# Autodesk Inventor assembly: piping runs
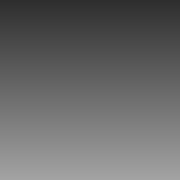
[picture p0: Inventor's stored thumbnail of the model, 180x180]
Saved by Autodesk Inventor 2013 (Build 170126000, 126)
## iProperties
ActiveState: False
BendRadius: UnInitValue
CouplingKey: v3#d2599e7a-1865-48da-a234-5418a1cd5dfe#3
DefaultBendRadius: UnInitValue
Diameter: 1/2
DiameterType: Nominal
Elbow45Key: v3#6ce5b1be-37aa-4928-b23a-0df64e6ddf38#2
Elbow90Key: v3#9fba244e-81ed-4fc6-a9ac-7eb372fa3ffe#3
ElbowCustomKey: UnInitValue
EndFittingKey: UnInitValue
Ending: UnInitValue
FittingMaterial: UnInitValue
FittingStandard: UnInitValue
FlangeKey: UnInitValue
Gap: UnInitValue
GasketKey: UnInitValue
ID: UnInitValue
IntermediateSegmentsInc: 2,540 mm
IntermediateSegmentsMax: 5080,000 mm
IntermediateSegmentsMin: 50,800 mm
IsButtWelded: False
IsFlanged: False
IsSelfDraining: False
Material: UnInitValue
MixedUnits: False
Name: DIN 2458/DIN EN 10242 - Stahlrohr mit Gewinde und Stahl-Fittings
OD: UnInitValue
PipeKey: v3#d689fd5f-ac5a-46d7-a883-3089b2f6e0a4#28
PipeType: Rigid Pipe
PipingComponentColor: As Material
RoundUpValue: UnInitValue
RouteDirection45: True
RouteDirection90: True
Schedule: ID=12.3
ShowGap: UnInitValue
Standard: UnInitValue
StartFittingKey: UnInitValue
SuppressEndFitting: UnInitValue
SuppressStartFitting: UnInitValue
TerminationSegmentsInc: 2,540 mm
TerminationSegmentsMax: 5080,000 mm
TerminationSegmentsMin: 50,800 mm
UseFlangsForCouplings: UnInitValue
UseSubASM: UnInitValue
_ComponentInfo: <CS><C N="Pipe" R="1.065000" IR="0.615000" PL="PL" PN="DIN 2458 Pipe with Threaded Ends 21.3 x 4.5"><CO N="1"><FE V="0"/><FD V="1"/><ET V="Threaded"/><NS V="1/2
CouplingKey: v3#eaa8de87-dc67-4eca-ba7e-4267a30f8f7f#2
Diameter: M40
Elbow45Key: v3#2769403e-a4fd-4a4c-8e4c-659ea845bd78#2
Elbow90Key: v3#c4513a61-3106-4a78-baf9-a1badd100245#2
IntermediateSegmentsInc: 1,000 mm
IntermediateSegmentsMax: 2500,000 mm
IntermediateSegmentsMin: 60,000 mm
Name: JIS K 6741/JIS K 6739 - Verbundenes PVC-U-Rohr und Fittings
PipeKey: v3#45338dd0-af69-48c0-a2ed-8ade33a08701#5
Schedule: VP
TerminationSegmentsInc: 1,000 mm
TerminationSegmentsMax: 2500,000 mm
TerminationSegmentsMin: 60,000 mm
_ComponentInfo: <CS><C N="Pipe" R="2.400000" IR="2.040000" PL="PL" PN="JIS K 6741 Pipe VP 40"><CO N="1"><FE V="0"/><FD V="1"/><ET V="Jointed"/><NS V="M40"/><MA V="4.000000"/><M
CouplingKey: v3#12b64993-10e6-4915-8315-0c0cce209ad0#8
Elbow45Key: v3#28e76e79-e22c-40ab-8be2-ff545b1407c5#8
Elbow90Key: v3#1f65ece3-c41a-48d4-8661-909ed34ade86#8
IntermediateSegmentsMax: 5000,000 mm
Name: JIS G 3458/JIS B 2316 -  Geschweißtes Stahlrohr und Fittings
PipeKey: v3#da14b0ab-0b36-4851-8d66-8c9cd0bcbe86#23
Schedule: 80
TerminationSegmentsMax: 5000,000 mm
_ComponentInfo: <CS><C N="Pipe" R="2.430000" IR="1.920000" PL="PL" PN="JIS G 3458 Pipe 40 A x Sch 80"><CO N="1"><FE V="0"/><FD V="1"/><ET V="Welded"/><NS V="M40"/><MA V="0.0000
Elbow45Key: v3#81684a3f-f2a4-4fe6-95b1-f067ddead22f#1
Elbow90Key: v3#451ae64e-c79d-4cba-b533-c09b8090ecb2#1
IntermediateSegmentsInc: 10,000 mm
IntermediateSegmentsMax: 9000,000 mm
IntermediateSegmentsMin: 1000,000 mm
Name: ISO 2531 - Geflanschtes, verformbares Stahlrohr und Fittings
PipeKey: v3#f52fbdcb-ece8-4303-8b76-5dbe8c7f2f9c#16
Schedule: PN10
TerminationSegmentsInc: 10,000 mm
TerminationSegmentsMax: 9000,000 mm
TerminationSegmentsMin: 1000,000 mm
_ComponentInfo: <CS><C N="Pipe" R="2.700000" IR="2.000000" PL="PL" PN="ISO 2531 Pipe with Integrally Cast Flanges DN40 PN 10"><CO N="1"><FE V="0"/><FD V="0"/><ET V="Flanged"/><
CouplingKey: v3#181262db-c004-4877-bc40-c64b931a44f6#3
Elbow45Key: v3#960407aa-00b9-4d72-aae7-d50595845cfd#3
Elbow90Key: v3#6c92b367-65e9-486b-b952-db434ae2548d#3
IntermediateSegmentsMin: 20,000 mm
Name: JIS G 3442/JIS B 2301 Stahlrohr mit Gewinde und Stahl-Fittings
PipeKey: v3#9964fba4-9d5a-4d75-85a8-e38022ccdce1#2
Schedule: ID=16.1
TerminationSegmentsMin: 20,000 mm
_ComponentInfo: <CS><C N="Pipe" R="1.085000" IR="0.805000" PL="PL" PN="JIS G 3442 Pipe with Threaded Ends 21.7 x 2.8"><CO N="1"><FE V="0"/><FD V="1"/><ET V="Threaded"/><NS V="1
Angle: UnInitValue
BendRadius: 12,700 mm
CouplingKey: UnInitValue
Elbow45Key: UnInitValue
Elbow90Key: UnInitValue
EndFittingKey: v3#b50cb43e-68c0-48ac-8e25-7ef224ce0e6c#3
ID: 1,27
IntermediateSegmentsInc: UnInitValue
IntermediateSegmentsMax: UnInitValue
IntermediateSegmentsMin: UnInitValue
IsButtWelded: UnInitValue
IsFlanged: UnInitValue
IsSelfDraining: UnInitValue
MixedUnits: UnInitValue
Name: Hydraulikschlauch - Äußeres gerades Gewinde
OD: 2,2352
PipeKey: v3#d489867e-ac9b-47ea-b952-0a1b885f66be#4
PipeType: Flexible Hose
RoundUpValue: 3,175 mm
RouteDirection45: UnInitValue
RouteDirection90: UnInitValue
Schedule: ID=0.5
StartFittingKey: v3#b50cb43e-68c0-48ac-8e25-7ef224ce0e6c#3
SuppressEndFitting: False
SuppressStartFitting: False
TerminationSegmentsInc: UnInitValue
TerminationSegmentsMax: UnInitValue
TerminationSegmentsMin: UnInitValue
UseSubASM: True
_ComponentInfo: <CS><C N="Pipe" R="1.117600" OR="1.117600" IR="0.635000" PL="PL" PartType="" SymKey="" PN="Parker Hydraulic Hose - No Skive 1/2"><CO N="1"><FE V="0"/><FD V="0"/
CouplingKey: v3#29993622-4c6a-437e-8b8c-43a0846f8735#1
Elbow45Key: v3#d7b5d569-4a12-4d65-ba55-12203d6ac7ed#1
Elbow90Key: v3#25d2a8db-6517-4627-a5a4-9d27e4d26b9b#1
IntermediateSegmentsMax: 2540,000 mm
IntermediateSegmentsMin: 25,400 mm
Name: ASTM D 1785-ASTM D 2466 - Verbundenes PVC-Rohr und Fitting
PipeKey: v3#4bf12049-4375-491b-8f13-d4ee0c517c57#1
Schedule: 40
TerminationSegmentsMax: 2540,000 mm
TerminationSegmentsMin: 25,400 mm
_ComponentInfo: <CS><C N="Pipe" R="1.066800" IR="0.789940" PL="PL" PN="ASTM D 1785 Pipe 1/2 - Schedule 40"><CO N="1"><FE V="0"/><FD V="0"/><ET V="Jointed"/><NS V="1/2"/><MA V="
CouplingKey: v3#0dc1ae02-7bbf-4ccf-8498-581434b0a765#3
DefaultBendRadius: 50,800 mm
IntermediateSegmentsMin: 0,000 mm
Name: ASTM B 88-ASME B16.22 - Gelötetes Kupferrohr
PipeKey: v3#44b182c9-4bce-4825-bb4d-596143122252#7
PipeType: Tubing
RouteDirection45: False
Schedule: L
TerminationSegmentsMin: 0,000 mm
_ComponentInfo: <CS><C N="Pipe" R="0.793750" IR="0.692150" PL="PL" PN="ASTM B 88 Tube 1/2 - Type L"><CO N="1"><FE V="0"/><FD V="0"/><ET V="Soldered"/><NS V="1/2"/><MA V="2.5400
Angle: 92,00 grd
Diameter: 1
Elbow45Key: v3#bf26aa2a-f3dd-474c-8758-922a145c2b02#15
Elbow90Key: v3#3e93288f-9bb7-4e46-9d6b-544f8c20ca1c#3
ElbowCustomKey: v3#1f3bd44a-47ab-42f9-b3e0-74afa0c3f0ca#3
Gap: 2,388 mm
IntermediateSegmentsInc: 0.00001 in
IsButtWelded: True
IsSelfDraining: True
Name: ASME BPE - angeschweißt
PipeKey: v3#b10c956f-6fc6-429e-8056-0864a8581764#35
Schedule: ID=0.87
ShowGap: True
TerminationSegmentsInc: 0.00001 in
_ComponentInfo: <CS><C N="Pipe" R="1.270000" OR="1.270000" IR="1.104900" PL="PL" PartType="pipe" SymKey="" PN="ASTM A 269 Tube with Welded ends 1 x 0.87"><CO N="1"><FE V="2"/><
CouplingKey: v3#ed415c76-4cec-44a3-ba67-72e47bf70384#4
Elbow45Key: v3#2e5fd082-3851-4eb0-bde1-6c7078a7d72b#4
Elbow90Key: v3#82a08401-12d7-413b-b7f9-9cf3b607be7b#4
Name: ASTM A53/A53M-ASME B16.11 - Geschweißtes Stahlrohr
PipeKey: v3#4ce5e9fa-6da0-4801-ac02-ee7a0fb518d6#7
_ComponentInfo: <CS><C N="Pipe" R="1.066800" IR="0.789940" PL="PL" PN="ASTM A 53/A 53M Pipe 1/2 - Schedule 40"><CO N="1"><FE V="0"/><FD V="0"/><ET V="Welded"/><NS V="1/2"/><MA 
Diameter: 6
Elbow90Key: v3#6a678020-d9d9-4685-bba9-906b9a167083#10
FlangeKey: v3#c11442d2-c568-438f-a870-8ac9b5b636cb#10
GasketKey: v3#2a41914c-f5fb-4682-9c6a-1870d826d3d0#23
IntermediateSegmentsMin: 76,200 mm
IsFlanged: True
Name: ASTM A 53/A-ASME B16.5 - Geflanschtes Stahlrohr mit Gewinde
PipeKey: v3#c5bd7d28-cdb3-4507-9f3d-c2787d93fe8a#40
TerminationSegmentsMin: 76,200 mm
_ComponentInfo: <CS><C N="Elbow90" ER="21.590000" S1="21.590000" S2="21.590000" D1="0.000000" D2="0.000000" PartType="fitting" SymKey="ELFL"><CO N="1"><FE V="2"/><FD V="1"/><ET
FlangeKey: v3#24991861-26e3-4c21-a713-f46e314eddd5#10
Name: ASTM A 53/A 53M - Stahlrohr mit Stoßnaht/Flansch
PipeKey: v3#4ce5e9fa-6da0-4801-ac02-ee7a0fb518d6#77
UseFlangsForCouplings: False
_ComponentInfo: <CS><C N="Pipe" R="8.413750" OR="8.413750" IR="7.702550" PL="PL" PartType="pipe" SymKey="" PN="ASTM A 53/A 53M Pipe 6 - Schedule 40"><CO N="1"><FE V="2"/><FD V=
Elbow90Key: v3#97ecdcaf-8aa3-4fb0-8b6a-3da783de2ad5#108
Gap: 1,575 mm
Name: ASTM A 53/A-ASME B16.9 - Stahlrohr mit Stumpfnaht
_ComponentInfo: <CS><C N="Elbow90" ER="15.240000" S1="15.240000" S2="15.240000" D1="0.000000" D2="0.000000" PartType="fitting" SymKey="ELBW"><CO N="1"><FE V="2"/><FD V="0"/><ET
ActiveState: True
CouplingKey: v3#52ad3977-2b89-4007-a6a6-7626bac0ae85#4
Elbow45Key: v3#5c2ab816-abcb-49a6-a106-4733af000f51#4
Elbow90Key: v3#160eac10-3e6f-4b5c-839c-61eee0d373dc#4
Name: ASME B36.10M-ASME B16.11 - Stahlrohr mit Gewinde
PipeKey: v3#4a736116-503a-44ad-a922-868ac6b46736#1
Schedule: 30
_ComponentInfo: <CS><C N="Pipe" R="1.066800" IR="0.825500" PL="PL" PN="ASME B36.10M Pipe with Threaded Ends 1/2 - Schedule 30"><CO N="1"><FE V="0"/><FD V="1"/><ET V="Threaded"/
Created: 2006-09
Part Number: piping runs
Document SubType Name: Tube & Pipe
Designer: Autodesk
Manufacturer: Standard
Standards Organization: Custom
EndFittingKey: v3#c8250148-a7b6-458b-b7bd-3b56763ca7cc#13
Name: Hydraulikschlauch - Äußeres Kegelgewinde
StartFittingKey: v3#c8250148-a7b6-458b-b7bd-3b56763ca7cc#13
EndFittingKey: v3#c5e461f5-5e73-4f2e-8c1e-4358d4d6f46c#4
Name: Hydraulikschlauch - Inneres Gewinde - geschwenkt
StartFittingKey: v3#c5e461f5-5e73-4f2e-8c1e-4358d4d6f46c#4
CouplingKey: v3#3edf83e2-464b-4b31-84c5-c329ffbf2a4f#5
Elbow45Key: v3#2f597a97-b15b-49d4-87cb-7bfe69eb62ee#5
Elbow90Key: v3#fbd68fd5-590c-4cb5-8c20-9e9bdd396a04#5
Name: DIN 8062/DIN 8063 - Verbundenes PVC-U-Rohr und Fittings
PipeKey: v3#3d294dc7-89c3-4c37-a0ae-28c15a73bfd0#13
Schedule: 5
_ComponentInfo: <CS><C N="Pipe" R="2.000000" IR="1.700000" PL="PL" PN="DIN 8062 Pipe 40 x 3"><CO N="1"><FE V="0"/><FD V="0"/><ET V="Jointed"/><NS V="M40"/><MA V="8.000000"/><MI
CouplingKey: v3#7e56b2cb-a132-4546-b8a7-a14538454b94#3
Elbow45Key: v3#a96c5204-26e4-4bb2-b8f1-f0623fbc94bb#2
Elbow90Key: v3#b72bb08b-ad33-47cc-a03d-7f3d76c6616b#3
Name: ISO 7598/ISO 49 - Stahlrohr mit Gewinde und Stahl-Fittings
PipeKey: v3#1052637f-74b5-47f4-adeb-d4e8d3fa53b8#1
_ComponentInfo: <CS><C N="Pipe" R="1.065000" IR="0.805000" PL="PL" PN="ISO 7598 Tube with Threaded Ends DN15"><CO N="1"><FE V="0"/><FD V="1"/><ET V="Threaded"/><NS V="1/2"/><MA
EndFittingKey: v3#cc3bd835-95a2-497d-9893-176cd9c426f6#7
Name: Hydraulikschlauch - Inneres Kegelgewinde
StartFittingKey: v3#cc3bd835-95a2-497d-9893-176cd9c426f6#7
CouplingKey: v3#b06656e5-2b55-488c-bcf0-6a90c79c4683#2
Elbow45Key: v3#421a8b99-1721-409a-bc3b-c00889561754#1
Elbow90Key: v3#17490b17-1dd8-40fc-8de7-1a70c3bab2d7#1
Name: ISO 4065-ISO 3633 - PVC-Rohr und Fittings
PipeKey: v3#4f84f716-5ba0-45ef-967a-c32c3d7345ce#70
Schedule: S40
_ComponentInfo: <CS><C N="Pipe" R="2.000000" IR="1.950000" PL="PL" PN="ISO 4065 Pipe 40 x 0.5 S40"><CO N="1"><FE V="0"/><FD V="0"/><ET V="Jointed"/><NS V="M40"/><MA V="6.000000
count: 53
Refkey_Axis1_Context: 2|0|0|0|1|0|0|0|
Refkey_Axis1: 6|0|0|0|44|0|0|0|78|0|65|0|77|0|69|0|83|0|10|0|67|0|111|0|108|0|111|0|114|0|115|0|10|0|49|0|58|0|10|0|10|0|69|0|78|0|68|0|10|0|0|0|
Refkey_Axis2_Context: 2|0|0|0|1|0|0|0|
Refkey_Axis2: 6|0|0|0|88|0|0|0|78|0|65|0|77|0|69|0|83|0|10|0|67|0|111|0|108|0|111|0|114|0|115|0|10|0|49|0|58|0|82|0|111|0|117|0|116|0|101|0|32|0|85|0|73|0|32|0|84|0|111|0|111
Refkey_Axis3_Context: 2|0|0|0|1|0|0|0|
Refkey_Axis3: 6|0|0|0|88|0|0|0|78|0|65|0|77|0|69|0|83|0|10|0|67|0|111|0|108|0|111|0|114|0|115|0|10|0|49|0|58|0|82|0|111|0|117|0|116|0|101|0|32|0|85|0|73|0|32|0|84|0|111|0|111
Refkey_Ext_Context: 2|0|0|0|1|0|0|0|
Refkey_Ext: 6|0|0|0|92|0|0|0|78|0|65|0|77|0|69|0|83|0|10|0|67|0|111|0|108|0|111|0|114|0|115|0|10|0|49|0|58|0|82|0|111|0|117|0|116|0|101|0|32|0|85|0|73|0|32|0|84|0|111|0|111
Refkey_Snap_Context: 2|0|0|0|1|0|0|0|
Refkey_Snap: 6|0|0|0|84|0|0|0|78|0|65|0|77|0|69|0|83|0|10|0|67|0|111|0|108|0|111|0|114|0|115|0|10|0|49|0|58|0|82|0|111|0|117|0|116|0|101|0|32|0|85|0|73|0|32|0|84|0|111|0|111
EndFittingKey: v3#933069c9-73b6-4141-af99-628d4a97b2c2#1
Name: Hydraulikschlauch - SAE-Flansch-Verbindung
StartFittingKey: v3#933069c9-73b6-4141-af99-628d4a97b2c2#1
Name: Hydraulikschlauch - Ohne Fittings
SuppressEndFitting: True
SuppressStartFitting: True
CouplingKey: v3#771d4942-b9e7-43bc-9d41-ab12a9580492#3
Elbow45Key: v3#626cc28c-1a24-4045-be0d-40d896dc828d#3
Elbow90Key: v3#bc6b44ab-9235-4590-b699-74498030a1ff#3
Name: ANSI/ASME B36.19M-ASME B16.3 - Rohr mit Gewinde und Stahl-Fittings
PipeKey: v3#323c0148-c750-449d-a0c6-11721f2a5046#1
Schedule: 40S
_ComponentInfo: <CS><C N="Pipe" R="1.066800" IR="0.789940" PL="PL" PN="ANSI/ASME B36.19M Pipe with Threaded Ends 1/2 - Schedule 40S"><CO N="1"><FE V="0"/><FD V="1"/><ET V="Thre
Author: Autodesk
Elbow45Key: v3#97879d80-057e-491b-840b-74a9b3a7cf63#17
Elbow90Key: v3#ace818b0-7b7c-4ad9-b19c-6da358a202c1#17
Name: DIN 2458/DIN 2605 - Geschweißtes Stahlrohr und Fittings
PipeKey: v3#dcef2839-8903-4c98-a96c-b861f5d9bb7f#98
Schedule: ID=30.7
_ComponentInfo: <CS><C N="Pipe" R="2.415000" IR="1.535000" PL="PL" PN="DIN 2458 Pipe 48.3 x 8.8"><CO N="1"><FE V="2"/><FD V="0"/><ET V="Welded"/><NS V="M40"/><MA V="0.000000"/>
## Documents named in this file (1)
- C:\Users\x86 deu\Desktop\MMM\piping runs.iam
